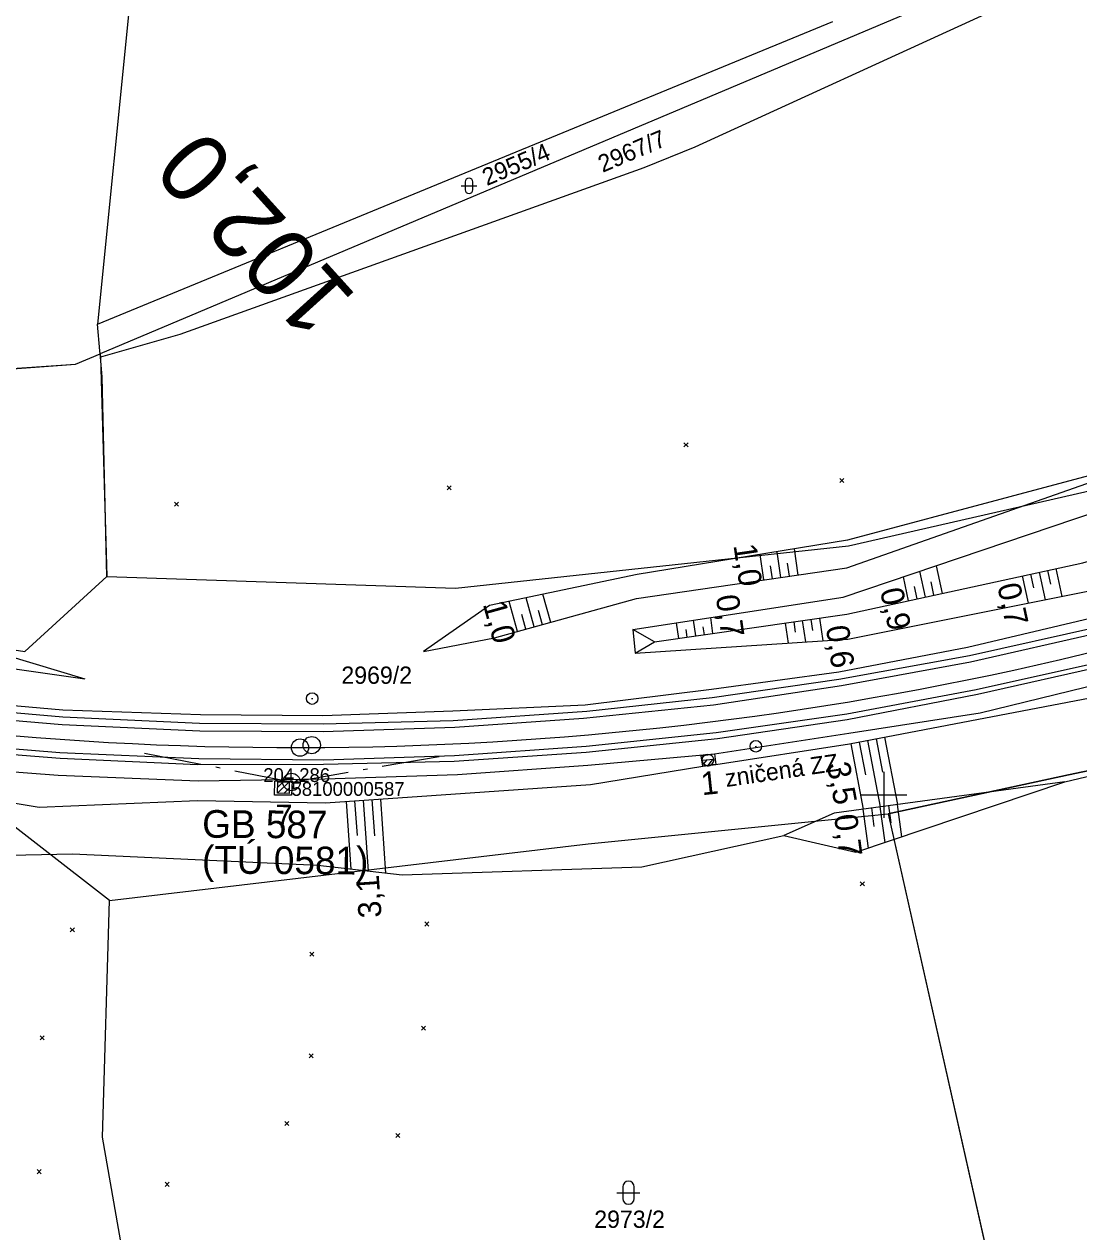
# Model space of a CAD drawing. Extents: x -800194 to -799078, y -1007177 to -1006597.
# Drawn here: x -799674.6 to -799583.1, y -1007037.9 to -1006933.1 of the extents above; entities that cross this region are included whole.
import ezdxf

# ---------------------------------------------------------------- set-up
doc = ezdxf.new("R2010")
doc.units = 0
for name, color, linetype in [('02_Osa_koleje', 7, 'Continuous'), ('_Vrstva 7 - Přesunutá', 7, 'Continuous'), ('Ramove udaje', 7, 'Continuous'), ('Vrstva 11', 7, 'Continuous'), ('Vrstva 12', 7, 'Continuous'), ('Vrstva 4', 7, 'Continuous'), ('Vrstva 48', 7, 'Continuous'), ('Vrstva 49', 7, 'Continuous'), ('Vrstva 50', 7, 'Continuous'), ('Vrstva 53', 7, 'Continuous'), ('Vrstva 55', 7, 'Continuous'), ('Vrstva 57', 7, 'Continuous'), ('Vrstva 58', 7, 'Continuous'), ('Vrstva 60', 7, 'Continuous'), ('Vrstva 61', 7, 'Continuous'), ('Vrstva 63', 7, 'Continuous'), ('Vrstva 7', 7, 'Continuous')]:
    doc.layers.add(name, color=color, linetype=linetype)

msp = doc.modelspace()

# ---------------------------------------------------------------- linework, layer by layer
at = {"layer": '02_Osa_koleje'}
msp.add_arc((-799651.02, -1006703.89), 292, 255.6249, 308.2052, dxfattribs=at)
at = {"layer": '_Vrstva 7 - Přesunutá'}
msp.add_circle((-799650.67, -1006995.89), 0.75, dxfattribs=at)
at = {"layer": 'Ramove udaje'}
for p, q in [((-799600, -1006998), (-799600, -1007002)), ((-799602, -1007000), (-799600, -1007000)), ((-799600, -1007000), (-799598, -1007000))]:
    msp.add_line(p, q, dxfattribs=at)
at = {"layer": 'Vrstva 11'}
for p, q in [((-799614.76, -1006996.92), (-799615.76, -1006997.02)), ((-799615.27, -1006997.47), (-799614.83, -1006996.92)), ((-799615.62, -1006997.31), (-799615.35, -1006996.98)), ((-799652.62, -1006999.86), (-799651.61, -1006998.87)), ((-799652.61, -1006999.33), (-799652.14, -1006998.87)), ((-799652.09, -1006999.87), (-799651.62, -1006999.4))]:
    msp.add_line(p, q, dxfattribs=at)
msp.add_lwpolyline([(-799652.61, -1006998.86), (-799651.61, -1006998.87), (-799651.62, -1006999.87), (-799652.62, -1006999.86)], close=True, dxfattribs=at)
msp.add_circle((-799615.26, -1006996.97), 0.503, dxfattribs=at)
msp.add_arc((-799615.26, -1006996.97), 0.503, 186.0853, 6.0853, dxfattribs=at)
at = {"layer": 'Vrstva 12'}
for points in [[(-799615.84, -1006996.62), (-799614.69, -1006996.42), (-799614.57, -1006997.35), (-799615.7, -1006997.51), (-799615.84, -1006996.62)], [(-799614.69, -1006996.42), (-799614.57, -1006997.35), (-799615.7, -1006997.51), (-799615.84, -1006996.62), (-799614.69, -1006996.42)], [(-799615.84, -1006996.62), (-799615.84, -1006996.62)], [(-799614.69, -1006996.42), (-799614.69, -1006996.42)], [(-799615.7, -1006997.51), (-799615.7, -1006997.51)], [(-799614.57, -1006997.35), (-799614.57, -1006997.35)], [(-799652.9, -1007000.02), (-799652.85, -1006998.81), (-799651.35, -1006998.78), (-799651.4, -1007000.01), (-799652.9, -1007000.02)]]:
    msp.add_lwpolyline(points, dxfattribs=at)
at = {"layer": 'Vrstva 4'}
for points in [[(-799766.32, -1006970.57), (-799760.95, -1006972.54), (-799747.64, -1006977.46), (-799730.55, -1006982.98), (-799710.07, -1006987.58), (-799704.73, -1006988.35), (-799693, -1006990.37), (-799682.43, -1006991.64), (-799671.27, -1006992.62), (-799659.31, -1006993.03), (-799648.69, -1006993.12), (-799637.4, -1006992.7), (-799625.91, -1006992.18), (-799614.96, -1006990.83), (-799603.91, -1006989.31), (-799592.73, -1006987.17), (-799581.6, -1006984.55), (-799570.58, -1006981.6), (-799559.91, -1006978.22), (-799542.96, -1006972.25), (-799531.79, -1006967.66), (-799521.29, -1006962.19), (-799511.24, -1006957.13)], [(-799779.68, -1006964.3), (-799766.32, -1006970.57), (-799761.25, -1006973.18), (-799747.77, -1006978.42), (-799730.77, -1006983.8), (-799710.33, -1006988.71), (-799704.92, -1006989.74), (-799693.13, -1006991.41), (-799682.58, -1006992.93), (-799671.33, -1006993.88), (-799659.36, -1006994.45), (-799648.66, -1006994.5), (-799637.23, -1006994.13), (-799626.07, -1006993.34), (-799614.79, -1006992.17), (-799603.67, -1006990.51), (-799592.47, -1006988.45), (-799581.28, -1006985.92), (-799570.22, -1006983), (-799559.3, -1006979.61), (-799542.38, -1006973.48), (-799531.24, -1006968.77), (-799520.48, -1006963.76), (-799510.39, -1006958.54)], [(-799776.86, -1006969.09), (-799770.96, -1006971.65), (-799761.91, -1006975.65), (-799748.54, -1006980.78), (-799731.46, -1006986.21), (-799711.13, -1006991.05), (-799705.48, -1006992.16), (-799693.53, -1006994.08), (-799682.8, -1006995.38), (-799671.51, -1006996.32), (-799659.45, -1006996.85), (-799648.59, -1006996.95), (-799637.26, -1006996.57), (-799625.83, -1006995.77), (-799614.55, -1006994.59), (-799603.2, -1006992.95), (-799591.97, -1006990.86), (-799580.65, -1006988.34), (-799569.53, -1006985.31), (-799558.56, -1006981.95), (-799541.41, -1006975.74), (-799530.26, -1006971.07), (-799519.46, -1006966), (-799509.25, -1006960.72)], [(-799776.86, -1006969.09), (-799771.26, -1006971.98), (-799762.13, -1006976.09), (-799748.71, -1006981.29), (-799731.51, -1006986.35), (-799711.22, -1006991.46), (-799705.53, -1006992.59), (-799693.58, -1006994.54), (-799682.85, -1006995.9), (-799671.5, -1006996.81), (-799659.56, -1006997.36), (-799648.62, -1006997.34), (-799637.28, -1006997.07), (-799625.83, -1006996.3), (-799614.43, -1006995.11), (-799603.18, -1006993.47), (-799591.85, -1006991.26), (-799580.56, -1006988.7), (-799569.45, -1006985.75), (-799558.39, -1006982.39), (-799541.27, -1006976.23), (-799530.1, -1006971.51), (-799519.4, -1006966.36), (-799509.09, -1006961.13)], [(-799779.01, -1006963.02), (-799770.63, -1006967.94), (-799766.32, -1006970.57), (-799761.02, -1006972.82), (-799747.75, -1006977.97), (-799730.72, -1006983.27), (-799710.2, -1006988.11), (-799704.77, -1006989.18), (-799693.07, -1006990.96), (-799682.55, -1006992.24), (-799671.27, -1006993.22), (-799659.39, -1006993.77), (-799648.66, -1006993.82), (-799637.39, -1006993.53), (-799625.77, -1006992.73), (-799614.9, -1006991.54), (-799603.91, -1006989.96), (-799592.57, -1006987.89), (-799581.42, -1006985.42), (-799570.33, -1006982.33), (-799559.43, -1006979.07), (-799542.6, -1006973.01), (-799531.45, -1006968.25), (-799520.74, -1006963.21)], [(-799683.1, -1006997.41), (-799671.67, -1006998.28), (-799659.52, -1006998.78), (-799648.52, -1006998.59), (-799637.01, -1006998.22), (-799625.7, -1006997.42), (-799614.69, -1006996.42), (-799603.02, -1006994.65), (-799591.63, -1006992.87), (-799579.9, -1006990.02), (-799578.26, -1006989.41), (-799577.13, -1006989.11), (-799569.11, -1006986.79), (-799557.83, -1006983.31), (-799552.61, -1006982.23), (-799552.13, -1006982.09), (-799550.03, -1006981.64), (-799548.93, -1006981.25), (-799540.64, -1006978.12), (-799538.19, -1006977.21), (-799529.22, -1006973.34), (-799517.86, -1006968.17)]]:
    msp.add_lwpolyline(points, dxfattribs=at)
at = {"layer": 'Vrstva 48'}
for p, q in [((-799610.4, -1006981.35), (-799610.72, -1006979.14)), ((-799608.92, -1006981.13), (-799609.24, -1006978.9)), ((-799607.43, -1006980.92), (-799607.76, -1006978.66)), ((-799609.66, -1006981.24), (-799609.82, -1006980.13)), ((-799608.17, -1006981.02), (-799608.34, -1006979.9)), ((-799594.91, -1006982.51), (-799595.43, -1006980.12)), ((-799597.84, -1006983.15), (-799598.29, -1006981.09)), ((-799596.38, -1006982.83), (-799596.86, -1006980.6)), ((-799587.98, -1006981), (-799587.47, -1006983.36)), ((-799587.25, -1006980.84), (-799586.99, -1006982.03)), ((-799586.52, -1006980.68), (-799586, -1006983.07)), ((-799585.79, -1006980.52), (-799585.52, -1006981.72)), ((-799585.05, -1006980.36), (-799584.53, -1006982.77)), ((-799597.11, -1006982.99), (-799597.34, -1006981.92)), ((-799595.64, -1006982.67), (-799595.89, -1006981.52)), ((-799631.79, -1006985.83), (-799632.52, -1006983.21)), ((-799630.35, -1006985.43), (-799631.05, -1006982.9)), ((-799628.9, -1006985.03), (-799629.58, -1006982.59)), ((-799631.07, -1006985.63), (-799631.43, -1006984.34)), ((-799629.63, -1006985.23), (-799629.97, -1006983.99)), ((-799617.8, -1006986.42), (-799617.99, -1006985.08)), ((-799616.31, -1006986.2), (-799616.51, -1006984.85)), ((-799615.57, -1006986.1), (-799615.67, -1006985.42)), ((-799614.83, -1006985.99), (-799615.02, -1006984.62)), ((-799608.55, -1006985.09), (-799608.3, -1006986.83)), ((-799607.81, -1006984.98), (-799607.68, -1006985.88)), ((-799607.07, -1006984.87), (-799606.8, -1006986.73)), ((-799606.33, -1006984.77), (-799606.19, -1006985.72)), ((-799605.59, -1006984.66), (-799605.3, -1006986.63)), ((-799617.05, -1006986.31), (-799617.15, -1006985.64)), ((-799602.87, -1006995.56), (-799601.79, -1007001.23)), ((-799602.14, -1006995.42), (-799601.59, -1006998.27)), ((-799601.4, -1006995.28), (-799600.3, -1007001.03)), ((-799600.66, -1006995.14), (-799600.11, -1006998.03)), ((-799599.93, -1006994.99), (-799598.81, -1007000.83)), ((-799646.67, -1007000.57), (-799646.27, -1007006.43)), ((-799645.93, -1007000.51), (-799645.72, -1007003.51)), ((-799645.18, -1007000.46), (-799644.75, -1007006.6)), ((-799644.43, -1007000.41), (-799644.21, -1007003.55)), ((-799643.68, -1007000.36), (-799643.24, -1007006.78)), ((-799601.07, -1007001.13), (-799600.85, -1007002.75)), ((-799600.33, -1007001.03), (-799599.91, -1007004.12)), ((-799599.58, -1007000.93), (-799599.38, -1007002.41)), ((-799598.84, -1007000.83), (-799598.46, -1007003.63)), ((-799601.81, -1007001.24), (-799601.35, -1007004.61))]:
    msp.add_line(p, q, dxfattribs=at)
at = {"layer": 'Vrstva 49'}
for p, q in [((-799617.34, -1006969.45), (-799616.99, -1006969.8)), ((-799617.34, -1006969.8), (-799616.99, -1006969.45)), ((-799603.8, -1006972.55), (-799603.45, -1006972.9)), ((-799603.8, -1006972.9), (-799603.45, -1006972.55)), ((-799637.9, -1006973.19), (-799637.55, -1006973.54)), ((-799637.9, -1006973.54), (-799637.55, -1006973.19)), ((-799661.58, -1006974.6), (-799661.23, -1006974.96)), ((-799661.58, -1006974.96), (-799661.23, -1006974.6)), ((-799602.04, -1007007.53), (-799601.68, -1007007.88)), ((-799602.04, -1007007.88), (-799601.68, -1007007.53)), ((-799670.61, -1007011.54), (-799670.26, -1007011.89)), ((-799670.61, -1007011.89), (-799670.26, -1007011.54)), ((-799639.85, -1007011.02), (-799639.5, -1007011.38)), ((-799639.85, -1007011.38), (-799639.5, -1007011.02)), ((-799649.82, -1007013.65), (-799649.46, -1007014)), ((-799649.82, -1007014), (-799649.46, -1007013.65)), ((-799673.24, -1007020.91), (-799672.89, -1007021.26)), ((-799673.24, -1007021.26), (-799672.89, -1007020.91)), ((-799640.12, -1007020.07), (-799639.77, -1007020.42)), ((-799640.12, -1007020.42), (-799639.77, -1007020.07)), ((-799649.88, -1007022.46), (-799649.52, -1007022.81)), ((-799649.88, -1007022.81), (-799649.52, -1007022.46)), ((-799652, -1007028.33), (-799651.64, -1007028.69)), ((-799652, -1007028.69), (-799651.64, -1007028.33)), ((-799642.35, -1007029.36), (-799642, -1007029.71)), ((-799642.35, -1007029.71), (-799642, -1007029.36)), ((-799673.5, -1007032.51), (-799673.15, -1007032.86)), ((-799673.5, -1007032.86), (-799673.15, -1007032.51)), ((-799662.38, -1007033.61), (-799662.03, -1007033.96)), ((-799662.38, -1007033.96), (-799662.03, -1007033.61))]:
    msp.add_line(p, q, dxfattribs=at)
for points in [[(-799710.32, -1006994.82), (-799708.87, -1006995.03), (-799692.77, -1006997.82), (-799673.3, -1007001.05), (-799659.56, -1007000.48), (-799648.46, -1007000.69), (-799625.45, -1006999.1), (-799615.7, -1006997.51), (-799614.57, -1006997.35), (-799602.96, -1006995.58), (-799579.5, -1006991.09), (-799558.66, -1006984.76), (-799544.86, -1006980.11), (-799538.19, -1006977.21), (-799529.22, -1006973.34), (-799517.86, -1006968.17), (-799516.56, -1006967), (-799515.53, -1006966.51), (-799507.82, -1006962.78)], [(-799621.79, -1006985.66), (-799603.52, -1006982.85), (-799581.35, -1006975.36), (-799561.47, -1006968.16), (-799550.92, -1006965.64), (-799546.89, -1006968.39)], [(-799619.91, -1006986.72), (-799603.2, -1006984.32), (-799582.71, -1006979.85), (-799558.8, -1006972.84), (-799550.2, -1006969.86), (-799550.92, -1006965.64)], [(-799621.79, -1006985.66), (-799621.59, -1006987.7), (-799603.12, -1006986.49), (-799582.14, -1006982.3), (-799558.67, -1006975.25), (-799547.5, -1006971.75), (-799546.89, -1006968.39)], [(-799641.81, -1007006.94), (-799621, -1007006.24), (-799608.68, -1007003.52), (-799602.42, -1007004.97), (-799584.29, -1006998.85), (-799562.54, -1006993.68), (-799545.4, -1006986.65), (-799532.46, -1006982.15), (-799507.06, -1006970.25)], [(-799574.95, -1006970.38), (-799603.15, -1006977.91), (-799621.41, -1006980.87), (-799634.22, -1006983.56), (-799639.94, -1006987.57)], [(-799639.94, -1006987.57), (-799633.79, -1006986.38), (-799621.45, -1006982.97), (-799603.21, -1006980.3), (-799574.95, -1006970.38)], [(-799728.17, -1006980.61), (-799726.81, -1006975.49), (-799714.47, -1006979.16), (-799704.93, -1006981.25), (-799699.1, -1006983.47), (-799688.78, -1006985.76), (-799678.42, -1006987.22), (-799669.36, -1006989.92)], [(-799728.17, -1006980.61), (-799715.64, -1006982.84), (-799705.85, -1006983.74), (-799700.59, -1006985.51), (-799691.67, -1006987.25), (-799678.69, -1006988.6), (-799669.36, -1006989.92)], [(-799621.59, -1006987.7), (-799619.91, -1006986.72), (-799621.79, -1006985.66)], [(-799716.25, -1006997.26), (-799713.52, -1006997.46), (-799709.9, -1006999.81), (-799706.58, -1006999.54), (-799702.82, -1006999.61), (-799701.05, -1007000.94), (-799691.91, -1007002.76), (-799679.88, -1007005.3), (-799670.42, -1007005.11), (-799649.12, -1007006.1), (-799641.81, -1007006.94)], [(-799584.29, -1006998.85), (-799604.31, -1007001.58), (-799608.68, -1007003.52)]]:
    msp.add_lwpolyline(points, dxfattribs=at)
at = {"layer": 'Vrstva 50'}
msp.add_line((-799611.15, -1006995.79), (-799611.05, -1006995.78), dxfattribs=at)
msp.add_circle((-799611.1, -1006995.78), 0.5, dxfattribs=at)
at = {"layer": 'Vrstva 53'}
for points in [[(-799686.25, -1006963.73), (-799670.17, -1006962.64), (-799668.03, -1006961.74), (-799668, -1006962.02), (-799667.43, -1006981.06), (-799637.16, -1006982.06), (-799603.07, -1006978.39), (-799559.64, -1006968.48), (-799519.68, -1006952.01)], [(-799521.98, -1006977.8), (-799546.71, -1006987.83), (-799572.22, -1006995.8), (-799583.97, -1006998.26), (-799599.63, -1007001.65), (-799584.37, -1007069.36), (-799591.04, -1007071.48), (-799597.25, -1007073.58), (-799607.27, -1007078.7), (-799623.27, -1007096.82), (-799619.94, -1007099.79), (-799606.31, -1007085.7), (-799604.36, -1007100.23), (-799602.09, -1007115.59), (-799604.31, -1007116.28), (-799613.8, -1007119.26), (-799629.52, -1007122.44), (-799580.26, -1007176.65)]]:
    msp.add_lwpolyline(points, dxfattribs=at)
at = {"layer": 'Vrstva 55'}
for p, q in [((-799596.27, -1006931.47), (-799668.03, -1006961.74)), ((-799668.25, -1006959.17), (-799604.43, -1006932.91)), ((-799668, -1006962.02), (-799668.03, -1006961.74)), ((-799599.63, -1007001.65), (-799584.37, -1007069.36))]:
    msp.add_line(p, q, dxfattribs=at)
for points in [[(-799652.26, -1006884.27), (-799656.47, -1006891.91), (-799662.36, -1006908.86), (-799665.44, -1006931.17), (-799668.25, -1006959.17)], [(-799591.61, -1006929.95), (-799590.84, -1006932.11), (-799616.41, -1006943.81), (-799620.83, -1006945.58), (-799661.1, -1006960.05), (-799668, -1006962.02)], [(-799667.43, -1006981.06), (-799637.16, -1006982.06), (-799603.07, -1006978.39), (-799559.64, -1006968.48), (-799519.68, -1006952.01)], [(-799668.03, -1006961.74), (-799668.05, -1006961.46), (-799668.25, -1006959.17)], [(-799599.63, -1007001.65), (-799583.97, -1006998.26), (-799572.22, -1006995.8), (-799546.71, -1006987.83), (-799521.98, -1006977.8), (-799495.25, -1006963.74), (-799489.22, -1006959.79), (-799487.22, -1006958.47)], [(-799686.25, -1006963.73), (-799681.51, -1006963.46), (-799670.17, -1006962.64), (-799668.03, -1006961.74)], [(-799667.43, -1006981.06), (-799667.85, -1006963.74), (-799668, -1006962.02)], [(-799691.32, -1006984.61), (-799685.35, -1006985.87), (-799674.55, -1006987.57), (-799667.43, -1006981.06)], [(-799667.22, -1007009.16), (-799678.94, -1007000.07), (-799720.83, -1006992.39), (-799728.88, -1006993.59), (-799733.28, -1006992.13)], [(-799667.22, -1007009.16), (-799625.65, -1007004.23), (-799599.63, -1007001.65)], [(-799665.73, -1007041.59), (-799667.81, -1007029.7), (-799667.22, -1007009.16)]]:
    msp.add_lwpolyline(points, dxfattribs=at)
at = {"layer": 'Vrstva 58'}
for p, q in [((-799636.67, -1006947.15), (-799635.33, -1006947.15)), ((-799636.33, -1006946.82), (-799636.33, -1006947.49)), ((-799635.67, -1006947.49), (-799635.67, -1006946.82)), ((-799623.16, -1007034.51), (-799621.16, -1007034.51)), ((-799622.66, -1007034.01), (-799622.66, -1007035.01)), ((-799621.66, -1007035.01), (-799621.66, -1007034.01))]:
    msp.add_line(p, q, dxfattribs=at)
for centre, radius, start, end in [((-799636, -1006946.82), 0.335, 0, 180), ((-799636, -1006947.49), 0.335, 180, 359.9879), ((-799622.16, -1007034.01), 0.5, 0, 180), ((-799622.16, -1007035.01), 0.5, 180, 359.9879)]:
    msp.add_arc(centre, radius, start, end, dxfattribs=at)
at = {"layer": 'Vrstva 60'}
msp.add_line((-799651.41, -1006998.88), (-799651.41, -1006998.88), dxfattribs=at)
at = {"layer": 'Vrstva 63'}
for p, q in [((-799659.27, -1006997.35), (-799664.17, -1006996.4)), ((-799643.53, -1006997.51), (-799638.6, -1006996.66)), ((-799657.6, -1006997.68), (-799657.99, -1006997.6)), ((-799651.41, -1006998.88), (-799656.32, -1006997.93)), ((-799645.2, -1006997.8), (-799644.81, -1006997.73)), ((-799651.46, -1006998.88), (-799651.36, -1006998.88)), ((-799651.41, -1006998.88), (-799646.49, -1006998.02))]:
    msp.add_line(p, q, dxfattribs=at)
msp.add_circle((-799651.41, -1006998.88), 0.756, dxfattribs=at)
at = {"layer": 'Vrstva 7'}
msp.add_line((-799649.67, -1006991.64), (-799649.57, -1006991.64), dxfattribs=at)
for centre, radius in [((-799649.62, -1006991.64), 0.5), ((-799649.65, -1006995.68), 0.75)]:
    msp.add_circle(centre, radius, dxfattribs=at)

# ---------------------------------------------------------------- texts
at = {"layer": 'Vrstva 11'}
for s, rotation, p in [('1', 6.0853, (-799615.76, -1007000.03)), ('7', 359.6337, (-799652.82, -1007002.84))]:
    msp.add_text(s, height=2, rotation=rotation, dxfattribs=at).set_placement(p)
at = {"layer": 'Vrstva 48'}
for s, rotation, p in [('1,0', 278.3433, (-799613.05, -1006978.34)), ('0,9', 282.3069, (-799600.34, -1006982.25)), ('0,7', 282.3069, (-799590.16, -1006981.84)), ('1,0', 285.4604, (-799634.81, -1006983.44)), ('0,7', 278.18, (-799614.59, -1006982.76)), ('0,6', 278.18, (-799605.03, -1006985.42)), ('3,5', 280.8184, (-799604.95, -1006997.33)), ('0,7', 277.7544, (-799604.32, -1007001.79)), ('3,1', 93.9585, (-799643.58, -1007010.61))]:
    msp.add_text(s, height=2, rotation=rotation, dxfattribs=at).set_placement(p)
at = {"layer": 'Vrstva 50'}
msp.add_text('zničená ZZ', height=1.5, rotation=8.2838, dxfattribs=at).set_placement((-799613.66, -1006999.32))
at = {"layer": 'Vrstva 57'}
for s, p in [('2967/7', (-799624.4, -1006946.03)), ('2955/4', (-799634.45, -1006947.18))]:
    msp.add_text(s, height=1.5, rotation=23, dxfattribs=at).set_placement(p)
for s, p in [('2969/2', (-799647.08, -1006990.36)), ('2973/2', (-799625.13, -1007037.56))]:
    msp.add_text(s, height=1.5, dxfattribs=at).set_placement(p)
at = {"layer": 'Vrstva 60'}
msp.add_text('58100000587', height=1.2, dxfattribs=at).set_placement((-799651.41, -1007000.08))
at = {"layer": 'Vrstva 61'}
msp.add_text('204.286', height=1.2, dxfattribs=at).set_placement((-799653.86, -1006998.88))
at = {"layer": 'Vrstva 63'}
for s, p in [('GB 587', (-799659.17, -1007003.71)), ('(TÚ 0581)', (-799659.19, -1007006.82))]:
    msp.add_text(s, height=2.4, rotation=359.6337, dxfattribs=at).set_placement(p)
at = {"layer": 'Vrstva 7'}
msp.add_text('102,0', height=6, rotation=132.1413, dxfattribs=at).set_placement((-799645.63, -1006956.83))

doc.saveas('drawing.dxf')
